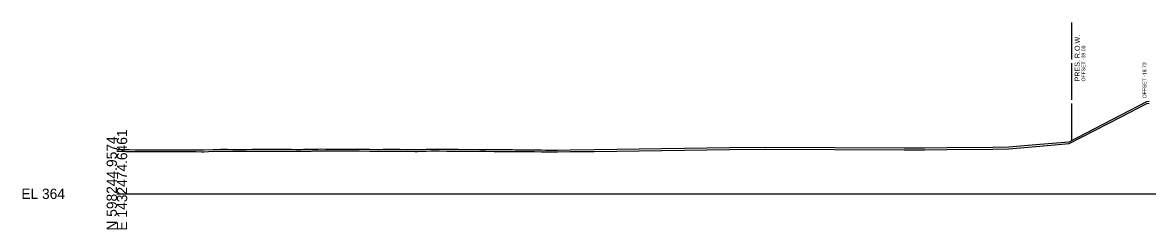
# Model space of a CAD drawing. Extents: x -26 to 2203, y -10 to 12201.
# Drawn here: x -25.7 to 280.6, y 2990.3 to 3046.5 of the extents above; entities that cross this region are included whole.
import ezdxf

# ---------------------------------------------------------------- set-up
doc = ezdxf.new("R2010")
doc.units = 0
for name, color, linetype in [('DESIGN - SHEET - Light Grid', 7, 'Continuous'), ('DESIGN - TYPICAL - Slope Tie Text', 7, 'Continuous'), ('SURVEY - GROUND - Bottom of Topsoil Layer', 7, 'Continuous'), ('SURVEY - GROUND - Top of Ground', 7, 'Continuous'), ('SURVEY - PROPERTY - ROW Lines', 7, 'Continuous'), ('SURVEY - PROPERTY - ROW Lines Text', 7, 'Continuous')]:
    doc.layers.add(name, color=color, linetype=linetype)

msp = doc.modelspace()

# ---------------------------------------------------------------- linework, layer by layer
at = {"layer": 'DESIGN - SHEET - Light Grid'}
msp.add_line((0, 3000), (300, 3000), dxfattribs=at)
at = {"layer": 'SURVEY - GROUND - Bottom of Topsoil Layer'}
for p, q in [((273.38, 3020.94), (280.44, 3024.56)), ((280.44, 3024.56), (281.03, 3024.67)), ((259.22, 3013.64), (273.38, 3020.94)), ((0, 3011.55), (0.52, 3011.55)), ((0.52, 3011.55), (2.37, 3011.52)), ((2.37, 3011.52), (3.38, 3011.5)), ((3.38, 3011.5), (5.02, 3011.47)), ((5.02, 3011.47), (7.77, 3011.46)), ((7.77, 3011.46), (14.59, 3011.49)), ((14.59, 3011.49), (15.76, 3011.49)), ((15.76, 3011.49), (20.93, 3011.45)), ((20.93, 3011.45), (21.49, 3011.45)), ((21.49, 3011.45), (23.1, 3011.42)), ((23.1, 3011.42), (23.64, 3011.42)), ((23.64, 3011.42), (26.23, 3011.55)), ((26.23, 3011.55), (28.27, 3011.63)), ((28.27, 3011.63), (30.11, 3011.61)), ((30.11, 3011.61), (31.53, 3011.56)), ((31.53, 3011.56), (33.25, 3011.58)), ((33.25, 3011.58), (34.18, 3011.57)), ((34.18, 3011.57), (35.21, 3011.57)), ((35.21, 3011.57), (36.83, 3011.62)), ((36.83, 3011.62), (37.17, 3011.61)), ((37.17, 3011.61), (38.15, 3011.62)), ((38.15, 3011.62), (39.48, 3011.61)), ((39.48, 3011.61), (40.2, 3011.61)), ((40.2, 3011.61), (42.13, 3011.6)), ((42.13, 3011.6), (44.3, 3011.61)), ((44.3, 3011.61), (44.78, 3011.61)), ((44.78, 3011.61), (45.68, 3011.6)), ((45.68, 3011.6), (47.43, 3011.6)), ((47.43, 3011.6), (48.94, 3011.58)), ((48.94, 3011.58), (50.08, 3011.58)), ((50.08, 3011.58), (50.9, 3011.62)), ((50.9, 3011.62), (52.86, 3011.63)), ((52.86, 3011.63), (53.2, 3011.64)), ((53.2, 3011.64), (54.82, 3011.67)), ((54.82, 3011.67), (55.38, 3011.68)), ((55.38, 3011.68), (56.78, 3011.65)), ((56.78, 3011.65), (58.04, 3011.65)), ((58.04, 3011.65), (58.74, 3011.64)), ((58.74, 3011.64), (60.73, 3011.65)), ((60.73, 3011.65), (62.66, 3011.65)), ((62.66, 3011.65), (63.34, 3011.66)), ((63.34, 3011.66), (64.75, 3011.67)), ((64.75, 3011.67), (65.99, 3011.67)), ((65.99, 3011.67), (68.85, 3011.62)), ((68.85, 3011.62), (71.29, 3011.57)), ((71.29, 3011.57), (72.46, 3011.59)), ((72.46, 3011.59), (73.94, 3011.61)), ((73.94, 3011.61), (74.42, 3011.61)), ((74.42, 3011.61), (75.78, 3011.63)), ((75.78, 3011.63), (76.59, 3011.63)), ((76.59, 3011.63), (77.03, 3011.62)), ((77.03, 3011.62), (79.24, 3011.55)), ((79.24, 3011.55), (81.12, 3011.54)), ((81.12, 3011.54), (81.89, 3011.53)), ((81.89, 3011.53), (83.31, 3011.58)), ((83.31, 3011.58), (84.22, 3011.61)), ((84.22, 3011.61), (85.59, 3011.64)), ((85.59, 3011.64), (86.18, 3011.65)), ((86.18, 3011.65), (87.71, 3011.64)), ((87.71, 3011.64), (89.84, 3011.6)), ((89.84, 3011.6), (91.53, 3011.6)), ((91.53, 3011.6), (92.89, 3011.62)), ((92.89, 3011.62), (98.78, 3011.58)), ((98.78, 3011.58), (99.72, 3011.58)), ((99.72, 3011.58), (100.45, 3011.56)), ((100.45, 3011.56), (102.69, 3011.54)), ((102.69, 3011.54), (105.89, 3011.51)), ((105.89, 3011.51), (107.74, 3011.52)), ((107.74, 3011.52), (108.4, 3011.49)), ((108.4, 3011.49), (109.7, 3011.47)), ((109.7, 3011.47), (111.05, 3011.46)), ((111.05, 3011.46), (113.7, 3011.49)), ((113.7, 3011.49), (115.59, 3011.43)), ((115.59, 3011.43), (116.69, 3011.38)), ((116.69, 3011.38), (117.55, 3011.37)), ((117.55, 3011.37), (117.94, 3011.37)), ((117.94, 3011.37), (119.97, 3011.38)), ((119.97, 3011.38), (123.38, 3011.48)), ((123.38, 3011.48), (129.92, 3011.51)), ((129.92, 3011.51), (166.82, 3012.07)), ((166.82, 3012.07), (176.5, 3012.16)), ((176.5, 3012.16), (214.35, 3011.97)), ((214.35, 3011.97), (219.91, 3011.95)), ((219.91, 3011.95), (225.98, 3012.05)), ((225.98, 3012.05), (238.51, 3012.16)), ((238.51, 3012.16), (242.87, 3012.22)), ((242.87, 3012.22), (251.23, 3012.97)), ((251.23, 3012.97), (259.22, 3013.64))]:
    msp.add_line(p, q, dxfattribs=at)
at = {"layer": 'SURVEY - GROUND - Top of Ground'}
for p, q in [((273.38, 3021.44), (280.44, 3025.06)), ((280.44, 3025.06), (281.03, 3025.17)), ((259.22, 3014.14), (273.38, 3021.44)), ((251.23, 3013.47), (259.22, 3014.14)), ((0, 3012.05), (0.52, 3012.05)), ((0.52, 3012.05), (2.37, 3012.02)), ((2.37, 3012.02), (3.38, 3012)), ((3.38, 3012), (5.02, 3011.97)), ((5.02, 3011.97), (7.77, 3011.96)), ((7.77, 3011.96), (14.59, 3011.99)), ((14.59, 3011.99), (15.76, 3011.99)), ((15.76, 3011.99), (20.93, 3011.95)), ((20.93, 3011.95), (21.49, 3011.95)), ((21.49, 3011.95), (23.1, 3011.92)), ((23.1, 3011.92), (23.64, 3011.92)), ((23.64, 3011.92), (26.23, 3012.05)), ((26.23, 3012.05), (28.27, 3012.13)), ((28.27, 3012.13), (30.11, 3012.11)), ((30.11, 3012.11), (31.53, 3012.06)), ((31.53, 3012.06), (33.25, 3012.08)), ((33.25, 3012.08), (34.18, 3012.07)), ((34.18, 3012.07), (35.21, 3012.07)), ((35.21, 3012.07), (36.83, 3012.12)), ((36.83, 3012.12), (37.17, 3012.11)), ((37.17, 3012.11), (38.15, 3012.12)), ((38.15, 3012.12), (39.48, 3012.11)), ((39.48, 3012.11), (40.2, 3012.11)), ((40.2, 3012.11), (42.13, 3012.1)), ((42.13, 3012.1), (44.3, 3012.11)), ((44.3, 3012.11), (44.78, 3012.11)), ((44.78, 3012.11), (45.68, 3012.1)), ((45.68, 3012.1), (47.43, 3012.1)), ((47.43, 3012.1), (48.94, 3012.08)), ((48.94, 3012.08), (50.08, 3012.08)), ((50.08, 3012.08), (50.9, 3012.12)), ((50.9, 3012.12), (52.86, 3012.13)), ((52.86, 3012.13), (53.2, 3012.14)), ((53.2, 3012.14), (54.82, 3012.17)), ((54.82, 3012.17), (55.38, 3012.18)), ((55.38, 3012.18), (56.78, 3012.15)), ((56.78, 3012.15), (58.04, 3012.15)), ((58.04, 3012.15), (58.74, 3012.14)), ((58.74, 3012.14), (60.73, 3012.15)), ((60.73, 3012.15), (62.66, 3012.15)), ((62.66, 3012.15), (63.34, 3012.16)), ((63.34, 3012.16), (64.75, 3012.17)), ((64.75, 3012.17), (65.99, 3012.17)), ((65.99, 3012.17), (68.85, 3012.12)), ((68.85, 3012.12), (71.29, 3012.07)), ((71.29, 3012.07), (72.46, 3012.09)), ((72.46, 3012.09), (73.94, 3012.11)), ((73.94, 3012.11), (74.42, 3012.11)), ((74.42, 3012.11), (75.78, 3012.13)), ((75.78, 3012.13), (76.59, 3012.13)), ((76.59, 3012.13), (77.03, 3012.12)), ((77.03, 3012.12), (79.24, 3012.05)), ((79.24, 3012.05), (81.12, 3012.04)), ((81.12, 3012.04), (81.89, 3012.03)), ((81.89, 3012.03), (83.31, 3012.08)), ((83.31, 3012.08), (84.22, 3012.11)), ((84.22, 3012.11), (85.59, 3012.14)), ((85.59, 3012.14), (86.18, 3012.15)), ((86.18, 3012.15), (87.71, 3012.14)), ((87.71, 3012.14), (89.84, 3012.1)), ((89.84, 3012.1), (91.53, 3012.1)), ((91.53, 3012.1), (92.89, 3012.12)), ((92.89, 3012.12), (98.78, 3012.08)), ((98.78, 3012.08), (99.72, 3012.08)), ((99.72, 3012.08), (100.45, 3012.06)), ((100.45, 3012.06), (102.69, 3012.04)), ((102.69, 3012.04), (105.89, 3012.01)), ((105.89, 3012.01), (107.74, 3012.02)), ((107.74, 3012.02), (108.4, 3011.99)), ((108.4, 3011.99), (109.7, 3011.97)), ((109.7, 3011.97), (111.05, 3011.96)), ((111.05, 3011.96), (113.7, 3011.99)), ((113.7, 3011.99), (115.59, 3011.93)), ((115.59, 3011.93), (116.69, 3011.88)), ((116.69, 3011.88), (117.55, 3011.87)), ((117.55, 3011.87), (117.94, 3011.87)), ((117.94, 3011.87), (119.97, 3011.88)), ((119.97, 3011.88), (123.38, 3011.98)), ((123.38, 3011.98), (129.92, 3012.01)), ((129.92, 3012.01), (166.82, 3012.57)), ((166.82, 3012.57), (176.5, 3012.66)), ((176.5, 3012.66), (214.35, 3012.47)), ((214.35, 3012.47), (219.91, 3012.45)), ((219.91, 3012.45), (225.98, 3012.55)), ((225.98, 3012.55), (238.51, 3012.66)), ((238.51, 3012.66), (242.87, 3012.72)), ((242.87, 3012.72), (251.23, 3013.47))]:
    msp.add_line(p, q, dxfattribs=at)
at = {"layer": 'SURVEY - PROPERTY - ROW Lines'}
for p, q in [((260, 3036.54), (260, 3046.54)), ((260, 3025.54), (260, 3035.54)), ((260, 3014.54), (260, 3024.54))]:
    msp.add_line(p, q, dxfattribs=at)

# ---------------------------------------------------------------- texts
at = {"layer": 'DESIGN - SHEET - Light Grid'}
for s, p in [('E 1432474.6461', (2.8, 2990)), ('N 598244.9574', (0, 2990))]:
    msp.add_text(s, height=2.8, rotation=90, dxfattribs=at).set_placement(p)
msp.add_text('EL 364', height=2.8, dxfattribs=at).set_placement((-26, 2998.6))
at = {"layer": 'DESIGN - TYPICAL - Slope Tie Text'}
msp.add_text('OFFSET -18.73', height=1, rotation=90, dxfattribs=at).set_placement((280.27, 3025.96))
at = {"layer": 'SURVEY - PROPERTY - ROW Lines Text'}
for s, height, p in [('PRES. R.O.W.', 1.4, (262.15, 3030.54)), ('OFFSET -39.00', 1, (263.65, 3030.54))]:
    msp.add_text(s, height=height, rotation=90, dxfattribs=at).set_placement(p)

doc.saveas('drawing.dxf')
